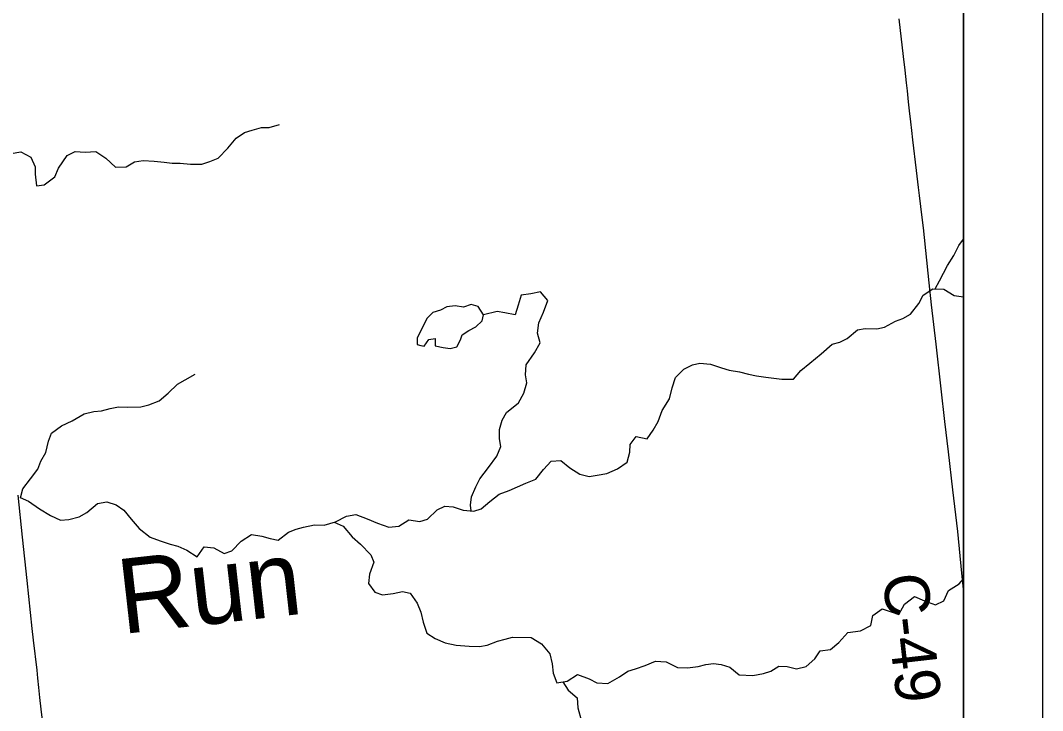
# Model space of a CAD drawing. Extents: x 0 to 34, y -5.4 to 22.
# Drawn here: x 7.705 to 9, y 15.618 to 16.492 of the extents above; entities that cross this region are included whole.
import ezdxf

# ---------------------------------------------------------------- set-up
doc = ezdxf.new("R2010")
doc.units = 0
for name, color, linetype in [('GM_X_County_Road', 7, 'Continuous'), ('GM_X_County_Road_Text', 7, 'Continuous'), ('GM_X_Minor_Lake', 7, 'Continuous'), ('GM_X_Minor_River', 7, 'Continuous'), ('GM_X_Minor_River_Text', 7, 'Continuous'), ('GM_X_Rail_Line', 7, 'Continuous'), ('GM_X_Township_Road', 7, 'Continuous'), ('SH_Data', 7, 'Continuous')]:
    doc.layers.add(name, color=color, linetype=linetype)

msp = doc.modelspace()

# ---------------------------------------------------------------- linework, layer by layer
at = {"layer": 'GM_X_County_Road'}
msp.add_lwpolyline([(8.9, 15.7716), (8.8978, 15.7921), (8.8925, 15.8446), (8.8861, 15.8976), (8.8806, 15.9457), (8.8761, 15.984), (8.8714, 16.0254), (8.865, 16.082), (8.8593, 16.132), (8.8564, 16.1598), (8.8491, 16.2295), (8.8476, 16.2426), (8.8459, 16.2567), (8.8441, 16.2706), (8.8428, 16.2807), (8.8402, 16.3023), (8.8357, 16.3411), (8.8343, 16.353), (8.8331, 16.3639), (8.8316, 16.3776), (8.8303, 16.3892), (8.8287, 16.4031), (8.8275, 16.4133), (8.8257, 16.4293), (8.8238, 16.4466), (8.8184, 16.4941)], dxfattribs=at)
at = {"layer": 'GM_X_Minor_Lake'}
for points in [[(8.2914, 16.1194), (8.2847, 16.1298), (8.276, 16.1322), (8.2661, 16.1289), (8.2555, 16.1306), (8.2453, 16.1292), (8.2369, 16.1252), (8.2274, 16.1223), (8.2197, 16.1148), (8.2157, 16.1058), (8.2076, 16.09), (8.2074, 16.0816), (8.212, 16.0806)], [(8.212, 16.0806), (8.2165, 16.0796), (8.2223, 16.0878), (8.2303, 16.0892), (8.2305, 16.0801), (8.2403, 16.0777), (8.2494, 16.0764), (8.2578, 16.0789), (8.2625, 16.0876), (8.2645, 16.094), (8.2729, 16.0992), (8.282, 16.104), (8.2897, 16.1115), (8.2914, 16.1194)]]:
    msp.add_lwpolyline(points, dxfattribs=at)
at = {"layer": 'GM_X_Minor_River'}
for points in [[(7.9555, 16.3177), (7.9675, 16.3304), (7.9783, 16.3431), (7.9886, 16.3501), (7.9985, 16.3534), (8.0103, 16.3566), (8.0201, 16.3568), (8.033, 16.3604)], [(7.693, 16.3237), (7.7051, 16.3258), (7.7179, 16.3191), (7.7234, 16.3069), (7.7236, 16.2974), (7.7252, 16.2829), (7.7347, 16.2839), (7.7485, 16.2939), (7.7532, 16.3052), (7.7641, 16.321), (7.774, 16.3261), (7.7869, 16.3255), (7.8005, 16.326), (7.8132, 16.3178), (7.8251, 16.3063), (7.8388, 16.3068), (7.8495, 16.313), (7.8605, 16.3148), (7.8741, 16.3141), (7.8869, 16.3128), (7.8971, 16.3115), (7.907, 16.3113), (7.9202, 16.3103), (7.9346, 16.3101), (7.9449, 16.3137), (7.9555, 16.3177)], [(8.864, 16.1521), (8.8692, 16.1624), (8.8743, 16.1722), (8.8797, 16.1819), (8.8875, 16.1943), (8.8937, 16.2071), (8.9, 16.215)], [(7.845, 15.8604), (7.8554, 15.8485), (7.8692, 15.8376), (7.8817, 15.8329), (7.8945, 15.8289), (7.9042, 15.826), (7.9155, 15.8213), (7.9286, 15.8127), (7.9375, 15.8255), (7.95, 15.8241), (7.9631, 15.8167), (7.9726, 15.8203), (7.9846, 15.8323), (7.9976, 15.8408), (8.0108, 15.839), (8.0213, 15.8358), (8.0315, 15.8337), (8.0446, 15.8437), (8.0541, 15.8478), (8.0636, 15.8503), (8.0773, 15.8531), (8.0897, 15.8528), (8.1042, 15.8571), (8.1179, 15.8641), (8.1297, 15.8662), (8.144, 15.8606), (8.1572, 15.8555), (8.1715, 15.8503), (8.1843, 15.8516), (8.197, 15.8597), (8.2109, 15.8576), (8.2204, 15.8605), (8.2327, 15.8724), (8.2427, 15.8768), (8.2532, 15.8758), (8.266, 15.8718), (8.2793, 15.8705), (8.2888, 15.8733), (8.2995, 15.8826), (8.3114, 15.8919), (8.324, 15.8966), (8.3453, 15.9061), (8.3579, 15.9112), (8.3676, 15.9232), (8.3772, 15.9337), (8.3897, 15.9346), (8.4009, 15.9253), (8.4136, 15.9175), (8.4253, 15.9146), (8.4356, 15.9163), (8.4477, 15.9184), (8.4614, 15.9242), (8.4737, 15.9328), (8.4769, 15.9452), (8.4775, 15.9551), (8.4852, 15.9652), (8.4988, 15.9623), (8.5065, 15.9732), (8.5131, 15.9841), (8.5179, 15.998), (8.5272, 16.0127), (8.5305, 16.0266), (8.5349, 16.0398), (8.5456, 16.0503), (8.5563, 16.0558), (8.5658, 16.0579), (8.5791, 16.0569), (8.593, 16.0521), (8.6028, 16.0493), (8.616, 16.0472), (8.6273, 16.044), (8.6375, 16.0419), (8.6495, 16.0402), (8.6594, 16.0389), (8.6696, 16.0379), (8.6843, 16.0377), (8.6936, 16.0489), (8.7051, 16.0582), (8.7193, 16.0697), (8.7335, 16.082), (8.743, 16.0845), (8.7525, 16.0892), (8.7656, 16.1004), (8.7751, 16.1021), (8.7902, 16.1015), (8.7997, 16.1036), (8.8135, 16.1113), (8.823, 16.1146), (8.8325, 16.1201), (8.8433, 16.1336), (8.8488, 16.1441), (8.8611, 16.1523), (8.8747, 16.1517), (8.8882, 16.1438), (8.9, 16.1419)], [(8.276, 15.8708), (8.2752, 15.8781), (8.2765, 15.8887), (8.2817, 15.9015), (8.2871, 15.9113), (8.298, 15.9259), (8.3084, 15.9401), (8.3136, 15.9526), (8.3118, 15.9621), (8.312, 15.9739), (8.3152, 15.9856), (8.3207, 15.9957), (8.336, 16.0076), (8.3427, 16.02), (8.3463, 16.0332), (8.3449, 16.0431), (8.3455, 16.056), (8.3564, 16.071), (8.3634, 16.0838), (8.3598, 16.096), (8.3616, 16.1092), (8.3678, 16.1228), (8.373, 16.1375), (8.3637, 16.1483), (8.3516, 16.1458), (8.3394, 16.1441), (8.3354, 16.1313), (8.3318, 16.1192), (8.3186, 16.1217), (8.3088, 16.1234), (8.2914, 16.1194)], [(7.705, 15.8876), (7.7079, 15.8988), (7.7176, 15.9116), (7.7269, 15.9236), (7.7308, 15.9337), (7.7371, 15.945), (7.7403, 15.959), (7.7443, 15.9695), (7.7569, 15.9788), (7.7703, 15.985), (7.7855, 15.9939), (7.7977, 15.9967), (7.8076, 15.9977), (7.8186, 16.0005), (7.8292, 16.0026), (7.8406, 16.0024), (7.8572, 16.0029), (7.8675, 16.0054), (7.8804, 16.0101), (7.8919, 16.0201), (7.9039, 16.0313), (7.9134, 16.0368), (7.9264, 16.0442)], [(7.7043, 15.8879), (7.7148, 15.8832), (7.7291, 15.8734), (7.7429, 15.8649), (7.7557, 15.8593), (7.7659, 15.8599), (7.7792, 15.8635), (7.7888, 15.869), (7.8026, 15.8801), (7.8144, 15.8822), (7.826, 15.8786), (7.8357, 15.8716), (7.845, 15.8604)], [(8.1025, 15.8566), (8.1136, 15.8513), (8.1251, 15.8382), (8.1359, 15.8285), (8.1489, 15.8154), (8.1525, 15.8059), (8.147, 15.7908), (8.1457, 15.7787), (8.1538, 15.7679), (8.1636, 15.7647), (8.1772, 15.766), (8.189, 15.7688), (8.1988, 15.7667), (8.2077, 15.7541), (8.212, 15.7426), (8.2152, 15.7297), (8.2199, 15.7159), (8.2304, 15.7093), (8.2428, 15.7038), (8.2571, 15.7009), (8.2734, 15.6995), (8.2866, 15.6989), (8.2961, 15.7006), (8.3091, 15.7057), (8.319, 15.7085), (8.3284, 15.7107), (8.3519, 15.7103), (8.365, 15.7024), (8.3758, 15.6897), (8.3786, 15.6772), (8.3799, 15.6654), (8.3843, 15.6532), (8.3975, 15.6552), (8.4105, 15.6637), (8.4256, 15.6582), (8.4353, 15.6531), (8.449, 15.6521), (8.4639, 15.6605), (8.4746, 15.6679), (8.4841, 15.6708), (8.4966, 15.6751), (8.5096, 15.6806), (8.5232, 15.6796), (8.5375, 15.6725), (8.55, 15.672), (8.5636, 15.6736), (8.5731, 15.6761), (8.583, 15.6775), (8.5928, 15.6762), (8.6037, 15.6729), (8.6157, 15.6632), (8.6327, 15.6622), (8.6463, 15.665), (8.6558, 15.6679), (8.6658, 15.6741), (8.6764, 15.6736), (8.6884, 15.6707), (8.7006, 15.6739), (8.7114, 15.6836), (8.718, 15.6934), (8.7312, 15.6954), (8.742, 15.7043), (8.7532, 15.7167), (8.7691, 15.719), (8.7825, 15.7256), (8.7849, 15.7385), (8.7968, 15.7466), (8.8081, 15.743), (8.8179, 15.7394), (8.8249, 15.7526), (8.8376, 15.7626), (8.8503, 15.7571), (8.8643, 15.7519), (8.8749, 15.7567), (8.8808, 15.7702), (8.8942, 15.7783), (8.9, 15.7848)], [(8.3922, 15.6544), (8.3989, 15.6438), (8.4104, 15.6341), (8.4113, 15.6212), (8.4158, 15.6045)]]:
    msp.add_lwpolyline(points, dxfattribs=at)
at = {"layer": 'GM_X_Rail_Line'}
msp.add_lwpolyline([(4.0439, 14.8538), (4.7395, 14.9295), (4.8765, 14.9444), (6.1164, 15.0793), (6.4403, 15.1171), (6.4463, 15.1177), (6.92, 15.1674), (6.9294, 15.1684), (6.9348, 15.169), (6.9914, 15.1749), (7.0389, 15.1799), (7.3134, 15.2082), (7.6796, 15.247), (7.6929, 15.2483), (7.8942, 15.2734), (7.8983, 15.2739), (8.1702, 15.3079), (8.1991, 15.5295), (8.9, 15.5944), (8.9, 19.2127)], dxfattribs=at)
at = {"layer": 'GM_X_Township_Road'}
for points in [[(7.7198, 15.722), (7.7132, 15.7827), (7.7075, 15.8375), (7.7021, 15.8906)], [(7.7718, 15.2845), (7.7706, 15.2881), (7.7693, 15.2918), (7.7686, 15.2952), (7.7658, 15.321), (7.763, 15.3464), (7.7601, 15.3729), (7.7558, 15.4106), (7.7489, 15.4699), (7.7366, 15.575), (7.7311, 15.6198), (7.7294, 15.6344), (7.728, 15.6469), (7.7268, 15.6591), (7.7258, 15.6691), (7.7214, 15.707), (7.7198, 15.722)]]:
    msp.add_lwpolyline(points, dxfattribs=at)
at = {"layer": 'SH_Data'}
for p, q in [((9, 21), (9, 14)), ((8.9, 20.9), (8.9, 14.1))]:
    msp.add_line(p, q, dxfattribs=at)

# ---------------------------------------------------------------- texts
at = {"layer": 'GM_X_County_Road_Text'}
msp.add_text('C-49', height=0.05682, rotation=276.5299, dxfattribs=at).set_placement((8.7971, 15.7889))
at = {"layer": 'GM_X_Minor_River_Text'}
msp.add_text('Run', height=0.09471, rotation=6.441, dxfattribs=at).set_placement((7.8337, 15.7147))

doc.saveas('drawing.dxf')
